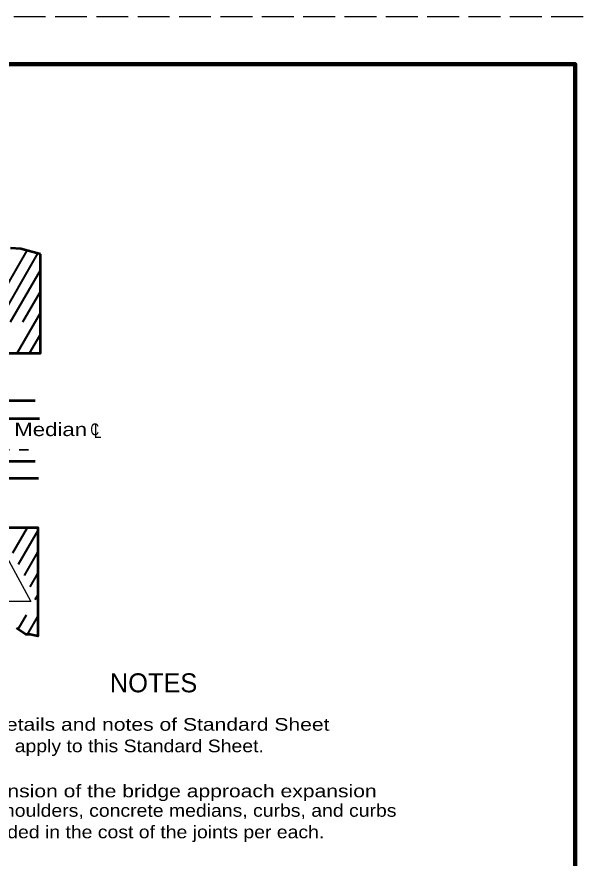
# Model space of a CAD drawing. Extents: x 14 to 49.3, y 28 to 50.
# Drawn here: x 43.21 to 49.18, y 41.18 to 50.04 of the extents above; entities that cross this region are included whole.
import ezdxf

# ---------------------------------------------------------------- set-up
doc = ezdxf.new("R2010")
doc.units = 0
doc.header["$LTSCALE"] = 0.056
doc.header["$PDMODE"] = 32
doc.header["$PDSIZE"] = 0.028
doc.linetypes.add('LONG_DASH_SHORT_DASH', pattern=[9.9, 6, -1.2, 1.5, -1.2])
doc.linetypes.add('LONG_DASHED', pattern=[7.5, 6, -1.5])
for name, color, linetype, lineweight in [('1', 7, 'Continuous', 35), ('3', 7, 'Continuous', 13), ('7', 7, 'LONG_DASH_SHORT_DASH', 35)]:
    doc.layers.add(name, color=color, linetype=linetype, lineweight=lineweight)

msp = doc.modelspace()

# ---------------------------------------------------------------- linework, layer by layer
at = {"layer": '1', "linetype": 'LONG_DASHED', "lineweight": 25}
msp.add_line((49.17658, 50.04392), (13.97658, 50.04392), dxfattribs=at)
at = {"layer": '1', "lineweight": 158}
msp.add_line((49.09325, 49.54392), (16.59325, 49.54392), dxfattribs=at)
at = {"layer": '1', "lineweight": 40}
for p, q in [((42.88075, 46.83067), (43.31367, 47.5805)), ((43.01067, 46.83067), (43.42575, 47.54975)), ((43.1405, 46.83067), (43.45375, 47.37325)), ((43.27042, 46.83067), (43.45375, 47.14825)), ((43.2085, 46.49817), (43.45375, 46.92325)), ((43.33825, 46.49817), (43.44742, 46.687)), ((43.16283, 44.39425), (43.3185, 44.664)), ((43.22375, 44.275), (43.42675, 44.6265)), ((43.28483, 44.15567), (43.42675, 44.4015)), ((43.34583, 44.03625), (43.42675, 44.1765)), ((43.39992, 43.90492), (43.42675, 43.9515)), ((43.2185, 43.59083), (43.30608, 43.7425)), ((43.31658, 43.5355), (43.42675, 43.7265))]:
    msp.add_line(p, q, dxfattribs=at)
at = {"layer": '1', "lineweight": 13}
msp.add_line((43.45117, 46.69375), (43.45375, 46.69825), dxfattribs=at)
at = {"layer": '1', "lineweight": 53}
for p, q in [((37.95883, 45.99975), (43.39992, 45.99975)), ((37.95883, 45.81167), (43.44475, 45.81167)), ((37.95883, 45.36017), (43.39992, 45.36017)), ((37.95883, 45.1815), (43.43575, 45.1815))]:
    msp.add_line(p, q, dxfattribs=at)
at = {"layer": '1', "lineweight": 158}
msp.add_lwpolyline([(49.09325, 49.54392), (49.09325, 28.54392), (16.59325, 28.54392)], dxfattribs=at)
at = {"layer": '1', "lineweight": 53}
for points in [[(43.45375, 47.54217), (43.24767, 47.59858), (43.14, 47.608)], [(37.94983, 46.34767), (37.94983, 46.49817), (43.45375, 46.49817), (43.45375, 47.54208)], [(37.95883, 44.664), (43.42675, 44.664), (43.42675, 43.51675), (43.34608, 43.5355), (43.30125, 43.5355), (43.20267, 43.60142)]]:
    msp.add_lwpolyline(points, dxfattribs=at)
at = {"layer": '1'}
msp.add_point((49.09325, 49.54392), dxfattribs=at)
at = {"layer": '3', "lineweight": 25}
msp.add_lwpolyline([(42.97908, 44.5655), (43.355, 43.8835), (42.70067, 43.8835)], dxfattribs=at)
at = {"layer": '7'}
msp.add_line((32.61783, 45.4825), (43.41783, 45.4825), dxfattribs=at)

# ---------------------------------------------------------------- texts
at = {"layer": '3'}
for s, height, width, p in [('Tapered-Flared Median ', 0.14, 1.25, (41.50083, 45.62617)), ('C', 0.126, 0.75, (43.98133, 45.63383)), ('L', 0.14, 0.75, (44.01808, 45.6055)), ('        The appropriate details and notes of Standard Sheet', 0.133, 1.25, (40.84158, 42.52158)), ('PVT5 (Sheet 1 of 2) shall apply to this Standard Sheet.', 0.133, 1.15, (40.84158, 42.29492)), ('        The cost of the extension of the bridge approach expansion ', 0.133, 1.25, (40.65942, 41.82017)), ('joints through concrete shoulders, concrete medians, curbs, and curbs ', 0.133, 1.15, (40.84158, 41.61492)), ('and gutters shall be included in the cost of the joints per each.', 0.133, 1.15, (40.84158, 41.38825))]:
    msp.add_text(s, height=height, dxfattribs=dict(at, width=width)).set_placement(p)
msp.add_text('NOTES', height=0.2, dxfattribs=at).set_placement((44.18667, 42.92633))

doc.saveas('drawing.dxf')
